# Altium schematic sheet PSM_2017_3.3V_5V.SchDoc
size Tabloid
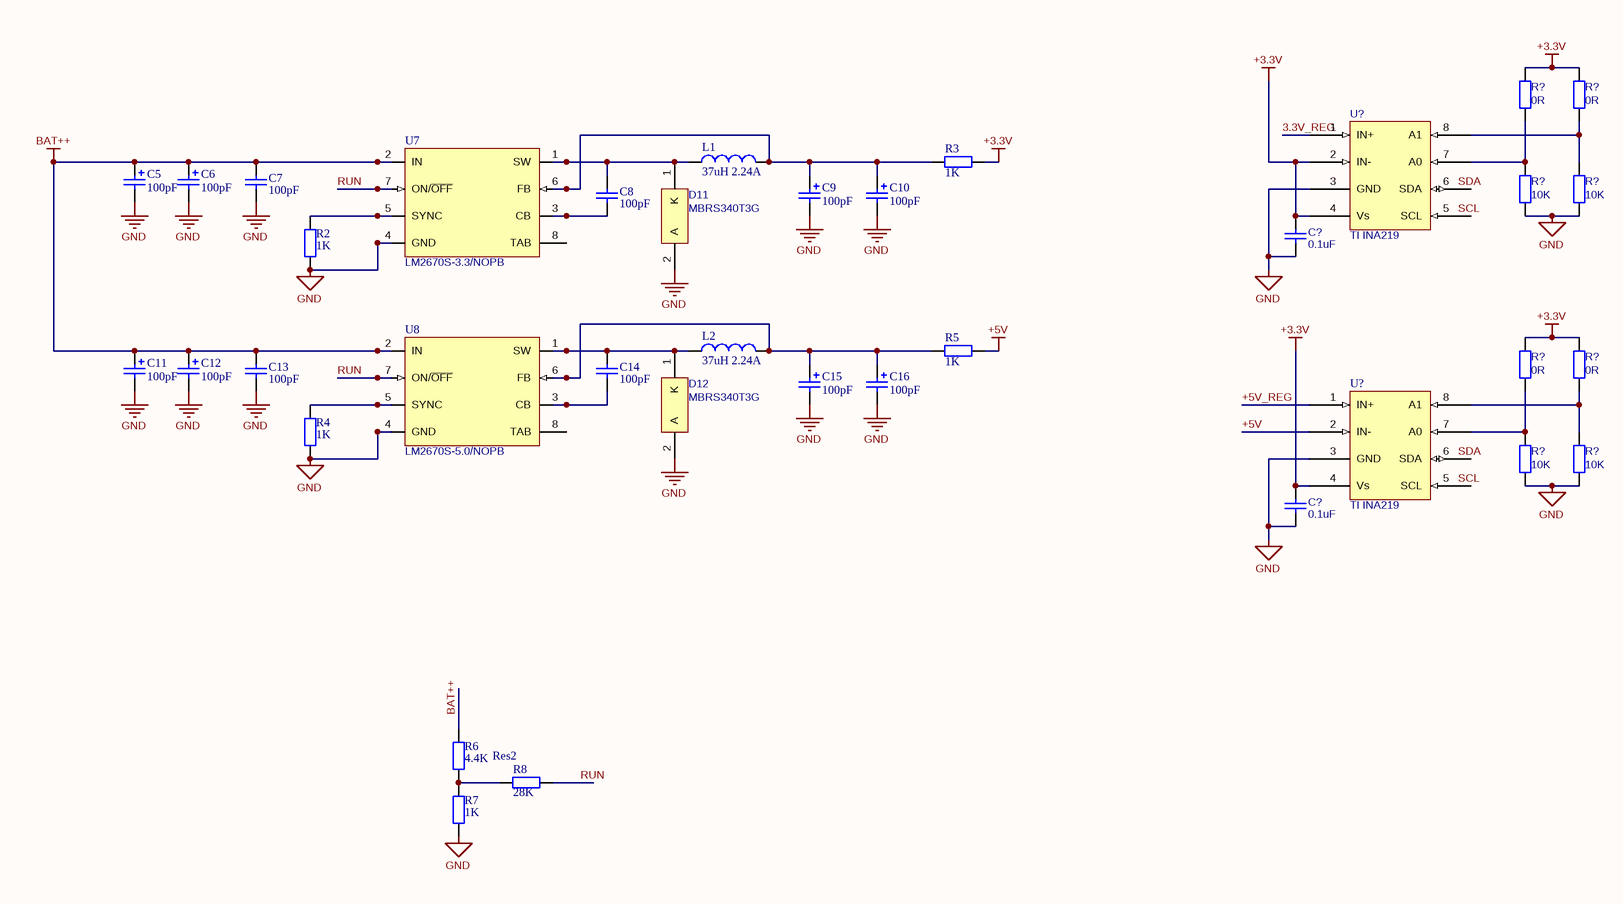
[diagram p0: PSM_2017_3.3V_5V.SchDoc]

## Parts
(Parts that share a designator on the sheet are numbered #1, #2 ... from top to bottom, then left to right.)
C5  value 100pF  [POLAR0.8]  (hidden comment: Cap Pol2)
C6  value 100pF  [POLAR0.8]  (hidden comment: Cap Pol2)
C7  value 100pF  [C1206]  (hidden comment: Cap Semi)
C8  value 100pF  [C1206]  (hidden comment: Cap Semi)
C9  value 100pF  [POLAR0.8]  (hidden comment: Cap Pol2)
C10  value 100pF  [POLAR0.8]  (hidden comment: Cap Pol2)
C11  value 100pF  [POLAR0.8]  (hidden comment: Cap Pol2)
C12  value 100pF  [POLAR0.8]  (hidden comment: Cap Pol2)
C13  value 100pF  [C1206]  (hidden comment: Cap Semi)
C14  value 100pF  [C1206]  (hidden comment: Cap Semi)
C15  value 100pF  [POLAR0.8]  (hidden comment: Cap Pol2)
C16  value 100pF  [POLAR0.8]  (hidden comment: Cap Pol2)
C?#1  value 0.1uF  [TDK CHIP CAP 2012(0805)]  (hidden comment: Cap Semi)
C?#2  value 0.1uF  [TDK CHIP CAP 2012(0805)]  (hidden comment: Cap Semi)
D11  MBRS340T3G  [ONSC-SMC-2-403-03_V]
D12  MBRS340T3G  [ONSC-SMC-2-403-03_V]
L1  37uH 2.24A  [Pulse Chip Inductor LCI-44]
L2  37uH 2.24A  [Pulse Chip Inductor LCI-44]
R2  value 1K  [AXIAL-0.4]  (hidden comment: Res2)
R3  value 1K  [AXIAL-0.4]  (hidden comment: Res2)
R4  value 1K  [AXIAL-0.4]  (hidden comment: Res2)
R5  value 1K  [AXIAL-0.4]  (hidden comment: Res2)
R6  value 4.4K  [AXIAL-0.4]  (hidden comment: Res2)
R7  value 1K  [AXIAL-0.4]  (hidden comment: Res2)
R8  Res2  value 28K  [AXIAL-0.4]
R?#1  value 0R  [RESC 2012 (0805) X06N]  (hidden comment: Res2)
R?#2  value 0R  [RESC 2012 (0805) X06N]  (hidden comment: Res2)
R?#3  value 10K  [RESC 2012 (0805) X06N]  (hidden comment: Res2)
R?#4  value 10K  [RESC 2012 (0805) X06N]  (hidden comment: Res2)
R?#5  value 0R  [RESC 2012 (0805) X06N]  (hidden comment: Res2)
R?#6  value 0R  [RESC 2012 (0805) X06N]  (hidden comment: Res2)
R?#7  value 10K  [RESC 2012 (0805) X06N]  (hidden comment: Res2)
R?#8  value 10K  [RESC 2012 (0805) X06N]  (hidden comment: Res2)
U7  LM2670S-3.3/NOPB  [TS7B_N]
U8  LM2670S-5.0/NOPB  [TS7B_N]
U?#1  TI INA219  [TI INA219 SOT-23]
U?#2  TI INA219  [TI INA219 SOT-23]

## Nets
+3.3V: C?#1.2 C?#2.2 R3.1 R?#1.2 R?#2.2 R?#5.2 R?#6.2 U?#1.2(IN-) U?#1.4(Vs) U?#2.4(Vs)
+5V: R5.1 U?#2.2(IN-)
BAT++: C5.1 C6.1 C7.2 C11.1 C12.1 C13.2 R6.2 U7.2(IN) U8.2(IN)
GND: C5.2 C6.2 C7.1 C9.2 C10.2 C11.2 C12.2 C13.1 C15.2 C16.2 C?#1.1 C?#2.1 D11.2(A) D12.2(A) R2.2 R4.2 R7.1 R?#3.2 R?#4.2 R?#7.2 R?#8.2 U7.4(GND) U8.4(GND) U?#1.3(GND) U?#2.3(GND)
3.3V_REG: U?#1.1(IN+)
+5V_REG: U?#2.1(IN+)
RUN: R8.1 U7.7(ON/~{OFF}) U8.7(ON/~{OFF})
NetC8_1: C8.1 U7.3(CB)
NetC8_2: C8.2 D11.1(K) L1.0 U7.1(SW)
NetC9_1: C9.1 C10.1 L1.1 R3.2 U7.6(FB)
NetC14_1: C14.1 U8.3(CB)
NetC14_2: C14.2 D12.1(K) L2.0 U8.1(SW)
NetC15_1: C15.1 C16.1 L2.1 R5.2 U8.6(FB)
NetR2_1: R2.1 U7.5(SYNC)
NetR4_1: R4.1 U8.5(SYNC)
NetR6_1: R6.1 R7.2 R8.2
NetR?#1_1: R?#1.1 R?#3.1 U?#1.7(A0)
NetR?#2_1: R?#2.1 R?#4.1 U?#1.8(A1)
NetR?#5_1: R?#5.1 R?#7.1 U?#2.7(A0)
NetR?#6_1: R?#6.1 R?#8.1 U?#2.8(A1)

Not connected (* = marked no-connect by the designer): U7 8(TAB); U8 8(TAB); U?#1 5(SCL) 6(SDA); U?#2 5(SCL) 6(SDA)

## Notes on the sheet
- Labels drawn without touching a wire or pin: SCL, SDA

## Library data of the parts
C5 C6 C9-C12 C15 C16 = Cap Pol2: Polarized Capacitor (Axial)
C7 C8 C13 C14 C?#1 C?#2 = Cap Semi: Capacitor (Semiconductor SIM Model)
D11 D12 = MBRS340T3G: Schottky Power Rectifier, 2-Pin SMC, Pb-Free, Tape and Reel; Manufacturer: On Semiconductor; Configuration: Single; IFSM Max (A): 80
L1 L2 = Pulse 37uH 2.24A: Pulse 37uH 2.24A 100mOHM, PE-53932SNLT
R2-R8 R?#1-R?#8 = Res2: Resistor
U7 = LM2670S-3.3/NOPB: SIMPLE SWITCHER® High Efficiency 3A Step-Down Voltage Regulator with Sync, 7-pin TO-263, Pb-Free; Manufacturer: National Semiconductor; PackageTopMarking: NSUZXYTTE#*LM2670*S-3.3; PowerWise: N; High-Reliability: Y
U8 = LM2670S-5.0/NOPB: SIMPLE SWITCHER® High Efficiency 3A Step-Down Voltage Regulator with Sync, 7-pin TO-263, Pb-Free; Manufacturer: National Semiconductor; PackageTopMarking: NSUZXYTTE#*LM2670*S-5.0; PowerWise: N; High-Reliability: Y
U?#1 U?#2 = TI INA219: Zerø-Drift, Bidirectional Current/Power Monitor With I  2C Interface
